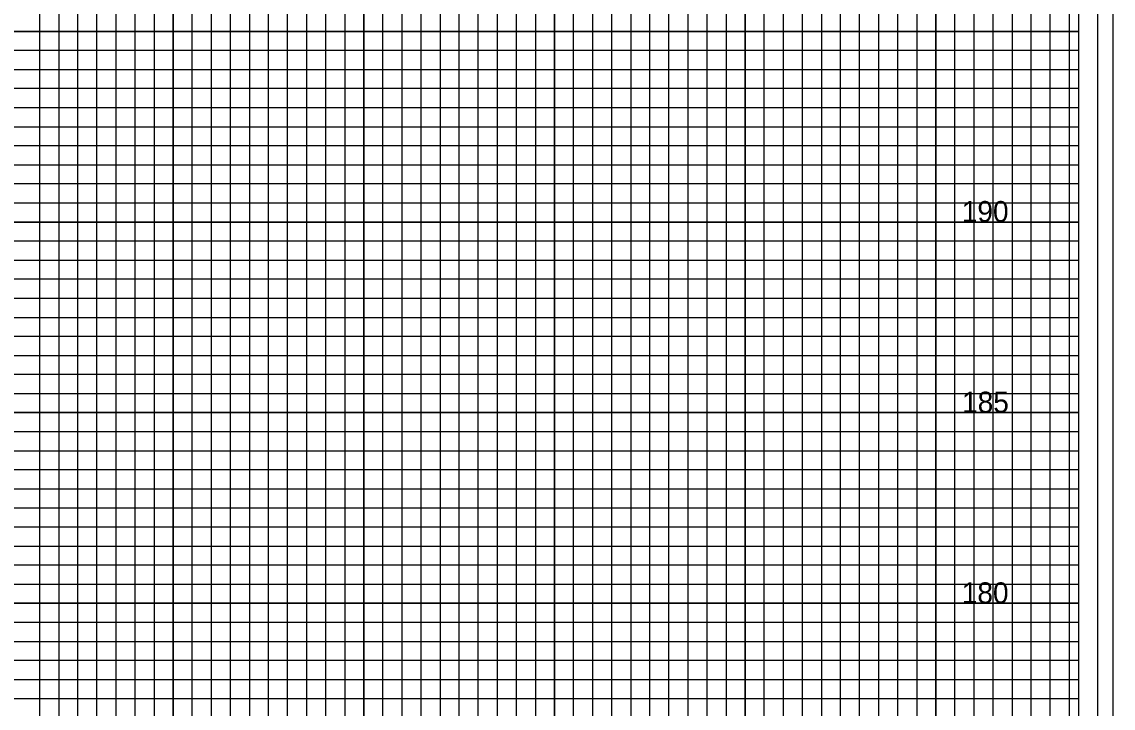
# Model space of a CAD drawing. Extents: x -4 to 103, y -2 to 67.
# Drawn here: x 74.78 to 103.4, y 32.25 to 50.25 of the extents above; entities that cross this region are included whole.
import ezdxf

# ---------------------------------------------------------------- set-up
doc = ezdxf.new("R2010")
doc.units = 0
for name, color, linetype in [('Old_Level_10', 7, 'Continuous'), ('Old_Level_4', 7, 'Continuous'), ('Old_Level_5', 7, 'Continuous'), ('Old_Level_6', 7, 'Continuous'), ('Old_Level_8', 7, 'Continuous'), ('Prop XS Dump Level', 7, 'Continuous'), ('Prop XSC Text', 7, 'Continuous')]:
    doc.layers.add(name, color=color, linetype=linetype)

msp = doc.modelspace()

# ---------------------------------------------------------------- linework, layer by layer
at = {"layer": 'Old_Level_10'}
for p, q in [((91.25, 0), (91.25, 63.425)), ((93.75, 0), (93.75, 63.425)), ((96.25, 0), (96.25, 63.425)), ((98.75, 0), (98.75, 63.425)), ((101.25, 0), (101.25, 63.425)), ((76.25, 0), (76.25, 62)), ((78.75, 0), (78.75, 62)), ((81.25, 0), (81.25, 62)), ((83.75, 0), (83.75, 62)), ((86.25, 0), (86.25, 62)), ((88.75, 0), (88.75, 62)), ((0, 50), (102.5, 50)), ((0, 47.5), (102.5, 47.5)), ((0, 45), (102.5, 45)), ((0, 42.5), (102.5, 42.5)), ((0, 40), (102.5, 40)), ((0, 37.5), (102.5, 37.5)), ((0, 35), (102.5, 35)), ((0, 32.5), (102.5, 32.5))]:
    msp.add_line(p, q, dxfattribs=at)
at = {"layer": 'Old_Level_4'}
msp.add_lwpolyline([(103, 66), (-2.8, 66), (-2.8, -1), (103, -1)], close=True, dxfattribs=at)
at = {"layer": 'Old_Level_5'}
msp.add_lwpolyline([(103.4, 67.4), (-3.5, 67.4), (-3.5, -2.425), (103.4, -2.425)], close=True, dxfattribs=at)
at = {"layer": 'Old_Level_6'}
msp.add_lwpolyline([(102.5, 65), (0, 65), (0, 0), (102.5, 0)], close=True, dxfattribs=at)
at = {"layer": 'Old_Level_8'}
for points in [[(91.25, 0), (91.25, 63.425), (93.75, 63.425), (93.75, 0)], [(96.25, 0), (96.25, 63.425), (98.75, 63.425), (98.75, 0)], [(101.25, 0), (101.25, 63.425)], [(76.25, 0), (76.25, 62), (78.75, 62), (78.75, 0)], [(81.25, 0), (81.25, 62), (83.75, 62), (83.75, 0)], [(86.25, 0), (86.25, 62), (88.75, 62), (88.75, 0)], [(0, 47.5), (102.5, 47.5), (102.5, 50), (0, 50)], [(0, 42.5), (102.5, 42.5), (102.5, 45), (0, 45)], [(0, 37.5), (102.5, 37.5), (102.5, 40), (0, 40)], [(0, 32.5), (102.5, 32.5), (102.5, 35), (0, 35)]]:
    msp.add_lwpolyline(points, dxfattribs=at)
at = {"layer": 'Prop XSC Text'}
for points in [[(90.25, 0), (90.25, 63.425), (90.75, 63.425), (90.75, 0)], [(91.75, 0), (91.75, 63.425), (92.25, 63.425), (92.25, 0)], [(92.75, 0), (92.75, 63.425), (93.25, 63.425), (93.25, 0)], [(94.25, 0), (94.25, 63.425), (94.75, 63.425), (94.75, 0)], [(95.25, 0), (95.25, 63.425), (95.75, 63.425), (95.75, 0)], [(96.75, 0), (96.75, 63.425), (97.25, 63.425), (97.25, 0)], [(97.75, 0), (97.75, 63.425), (98.25, 63.425), (98.25, 0)], [(99.25, 0), (99.25, 63.425), (99.75, 63.425), (99.75, 0)], [(100.25, 0), (100.25, 63.425)], [(100.25, 63.425), (100.75, 63.425), (100.75, 0), (101.75, 0), (101.75, 63.425), (102.25, 63.425), (102.25, 0)], [(75.25, 0), (75.25, 62), (75.75, 62), (75.75, 0)], [(76.75, 0), (76.75, 62), (77.25, 62), (77.25, 0)], [(77.75, 0), (77.75, 62), (78.25, 62), (78.25, 0)], [(79.25, 0), (79.25, 62), (79.75, 62), (79.75, 0)], [(80.25, 0), (80.25, 62), (80.75, 62), (80.75, 0)], [(81.75, 0), (81.75, 62), (82.25, 62), (82.25, 0)], [(82.75, 0), (82.75, 62), (83.25, 62), (83.25, 0)], [(84.25, 0), (84.25, 62), (84.75, 62), (84.75, 0)], [(85.25, 0), (85.25, 62), (85.75, 62), (85.75, 0)], [(86.75, 0), (86.75, 62), (87.25, 62), (87.25, 0)], [(87.75, 0), (87.75, 62), (88.25, 62), (88.25, 0)], [(89.25, 0), (89.25, 62), (89.75, 62), (89.75, 0)], [(0, 49), (102.5, 49), (102.5, 49.5), (0, 49.5)], [(0, 48), (102.5, 48), (102.5, 48.5), (0, 48.5)], [(0, 46.5), (102.5, 46.5), (102.5, 47), (0, 47)], [(0, 45.5), (102.5, 45.5), (102.5, 46), (0, 46)], [(0, 44), (102.5, 44), (102.5, 44.5), (0, 44.5)], [(0, 43), (102.5, 43), (102.5, 43.5), (0, 43.5)], [(0, 41.5), (102.5, 41.5), (102.5, 42), (0, 42)], [(0, 40.5), (102.5, 40.5), (102.5, 41), (0, 41)], [(0, 39), (102.5, 39), (102.5, 39.5), (0, 39.5)], [(0, 38), (102.5, 38), (102.5, 38.5), (0, 38.5)], [(0, 36.5), (102.5, 36.5), (102.5, 37), (0, 37)], [(0, 35.5), (102.5, 35.5), (102.5, 36), (0, 36)], [(0, 34), (102.5, 34), (102.5, 34.5), (0, 34.5)], [(0, 33), (102.5, 33), (102.5, 33.5), (0, 33.5)]]:
    msp.add_lwpolyline(points, dxfattribs=at)

# ---------------------------------------------------------------- texts
at = {"layer": 'Prop XS Dump Level'}
for s, p in [('190', (99.43, 45)), ('185', (99.438, 40)), ('180', (99.43, 35))]:
    msp.add_text(s, height=0.55, dxfattribs=at).set_placement(p)

doc.saveas('drawing.dxf')
